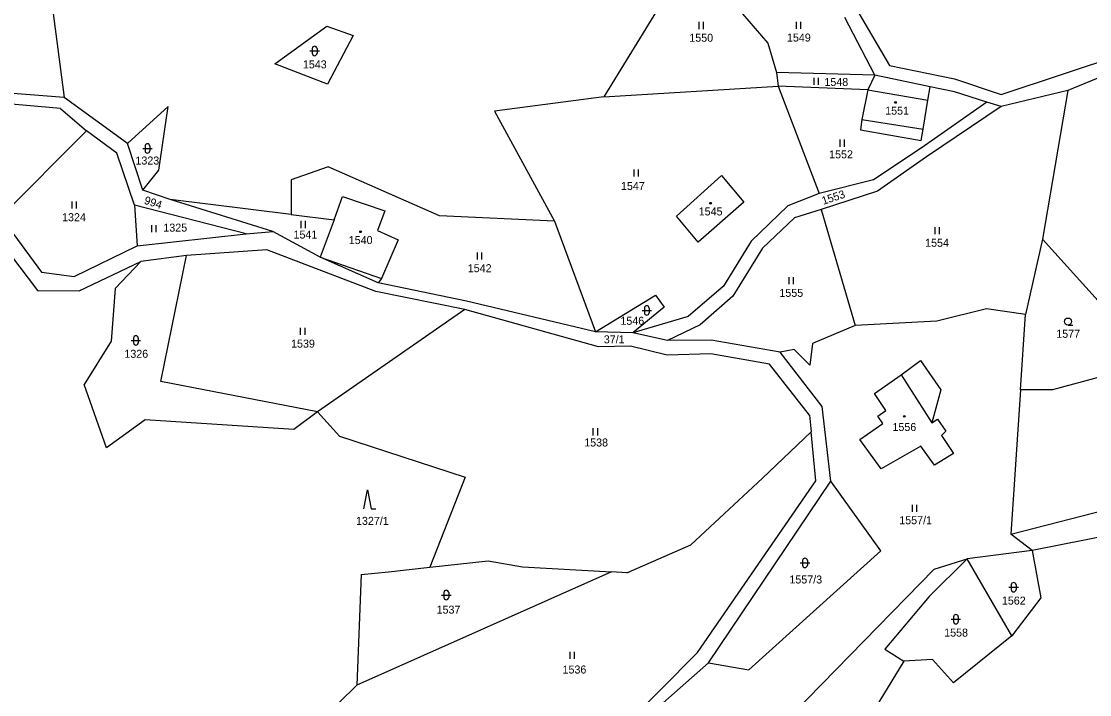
# Model space of a CAD drawing. Extents: x -670359 to -668019, y -978807 to -976674.
# Drawn here: x -669575.5 to -669348.5, y -978050.6 to -977907.6 of the extents above; entities that cross this region are included whole.
import ezdxf

# ---------------------------------------------------------------- set-up
doc = ezdxf.new("R2010")
doc.units = 0
for name, color, linetype in [('Hranice parcel', 7, 'Continuous'), ('Parcelní čísla', 7, 'Continuous'), ('Vnitřní kresba', 7, 'Continuous'), ('Značky budov', 7, 'Continuous'), ('Značky kultur', 7, 'Continuous')]:
    doc.layers.add(name, color=color, linetype=linetype)

msp = doc.modelspace()

# ---------------------------------------------------------------- linework, layer by layer
at = {"layer": 'Hranice parcel'}
for points in [[(-669572.17, -977879.31), (-669566.4, -977923.76)], [(-669430.35, -977896.52), (-669416.9, -977912.18)], [(-669435.8, -977897.58), (-669451.69, -977923.64)], [(-669394.16, -977918.98), (-669400.52, -977906.76)], [(-669397.47, -977905.99), (-669391.02, -977916.94)], [(-669521.65, -977916.57), (-669510.6, -977908.61)], [(-669510.6, -977908.61), (-669505.02, -977910.59)], [(-669505.02, -977910.59), (-669510.41, -977920.93)], [(-669416.9, -977912.18), (-669415.05, -977918.44)], [(-669367.31, -977923.11), (-669341.2, -977914.44)], [(-669510.41, -977920.93), (-669521.65, -977916.57)], [(-669391.02, -977916.94), (-669377.2, -977919.81)], [(-669339.55, -977916.69), (-669353.13, -977922.23)], [(-669415.05, -977918.44), (-669414.68, -977921.32)], [(-669394.16, -977918.98), (-669415.05, -977918.44)], [(-669394.16, -977918.98), (-669395.64, -977922.09)], [(-669382.38, -977921.45), (-669394.16, -977918.98)], [(-669451.69, -977923.64), (-669414.68, -977921.32)], [(-669414.68, -977921.32), (-669405.96, -977944.13)], [(-669395.64, -977922.09), (-669414.68, -977921.32)], [(-669382.85, -977924.3), (-669382.38, -977921.45)], [(-669377.23, -977922.53), (-669382.38, -977921.45)], [(-669377.2, -977919.81), (-669367.31, -977923.11)], [(-669566.4, -977923.76), (-669587.31, -977922.09)], [(-669552.97, -977933.51), (-669566.4, -977923.76)], [(-669451.69, -977923.64), (-669474.93, -977926.67)], [(-669395.64, -977922.09), (-669396.9, -977928.39)], [(-669370.37, -977924.76), (-669377.23, -977922.53)], [(-669353.13, -977922.23), (-669367.26, -977925.67)], [(-669353.13, -977922.23), (-669358.51, -977953.84)], [(-669567.14, -977926.07), (-669587.3, -977924.33)], [(-669567.14, -977926.07), (-669561.67, -977930.85)], [(-669544.32, -977925.68), (-669552.97, -977933.51)], [(-669546.31, -977939.18), (-669544.32, -977925.68)], [(-669370.37, -977924.76), (-669384.32, -977934.53)], [(-669383.88, -977930.45), (-669382.85, -977924.3)], [(-669367.26, -977925.67), (-669383.14, -977936.38)], [(-669367.26, -977925.67), (-669370.37, -977924.76)], [(-669474.93, -977926.67), (-669462.21, -977950)], [(-669396.9, -977928.39), (-669397.17, -977930.63)], [(-669397.17, -977930.63), (-669384.3, -977932.86)], [(-669384.3, -977932.86), (-669383.88, -977930.45)], [(-669561.67, -977930.85), (-669579.87, -977949.13)], [(-669555.23, -977935.56), (-669561.67, -977930.85)], [(-669549.71, -977943.46), (-669552.97, -977933.51)], [(-669384.32, -977934.53), (-669394.4, -977941.22)], [(-669551.43, -977946.64), (-669555.23, -977935.56)], [(-669383.14, -977936.38), (-669393.54, -977943.62)], [(-669549.71, -977943.46), (-669546.31, -977939.18)], [(-669510.28, -977938.45), (-669518.15, -977941.24)], [(-669486.61, -977948.86), (-669510.28, -977938.45)], [(-669518.15, -977941.24), (-669518.15, -977948.6)], [(-669436.26, -977949), (-669426.73, -977940.31)], [(-669426.73, -977940.31), (-669421.98, -977945.96)], [(-669394.4, -977941.22), (-669405.96, -977944.13)], [(-669543.89, -977945.44), (-669549.71, -977943.46)], [(-669405.96, -977944.13), (-669412.63, -977946.78)], [(-669393.54, -977943.62), (-669405.51, -977947.57)], [(-669527.72, -977952.73), (-669551.43, -977946.64)], [(-669551.43, -977946.64), (-669550.88, -977955.28)], [(-669518.15, -977948.6), (-669543.89, -977945.44)], [(-669522.03, -977952.24), (-669543.89, -977945.44)], [(-669509.04, -977949.72), (-669507.22, -977944.8)], [(-669507.22, -977944.8), (-669498.29, -977947.85)], [(-669421.98, -977945.96), (-669431.68, -977954.49)], [(-669518.15, -977948.6), (-669509.04, -977949.72)], [(-669498.29, -977947.85), (-669499.85, -977952)], [(-669462.21, -977950), (-669486.61, -977948.86)], [(-669412.63, -977946.78), (-669420.39, -977954.29)], [(-669405.51, -977947.57), (-669411.21, -977949.35)], [(-669405.51, -977947.57), (-669398.33, -977972.21)], [(-669579.87, -977949.13), (-669571.19, -977960.9)], [(-669509.04, -977949.72), (-669512, -977957.7)], [(-669462.21, -977950), (-669453.49, -977973.53)], [(-669431.68, -977954.49), (-669436.26, -977949)], [(-669411.21, -977949.35), (-669418.01, -977955.76)], [(-669581.59, -977952.23), (-669572.03, -977964.73)], [(-669550.88, -977955.28), (-669527.72, -977952.73)], [(-669527.72, -977952.73), (-669522.03, -977952.24)], [(-669512, -977957.7), (-669522.03, -977952.24)], [(-669499.85, -977952), (-669495.39, -977953.96)], [(-669564.24, -977961.78), (-669550.88, -977955.28)], [(-669495.39, -977953.96), (-669499, -977962.24)], [(-669420.39, -977954.29), (-669426.26, -977963.83)], [(-669358.51, -977953.84), (-669362.12, -977969.88)], [(-669334.85, -977980.09), (-669358.51, -977953.84)], [(-669540.41, -977957.32), (-669550.11, -977958.57)], [(-669545.82, -977984.13), (-669540.41, -977957.32)], [(-669523.35, -977956.14), (-669540.41, -977957.32)], [(-669500.15, -977964.95), (-669523.35, -977956.14)], [(-669499.65, -977963.12), (-669512, -977957.7)], [(-669418.01, -977955.76), (-669424.28, -977965.93)], [(-669563.23, -977964.83), (-669550.11, -977958.57)], [(-669550.11, -977958.57), (-669555.54, -977964.35)], [(-669571.19, -977960.9), (-669564.24, -977961.78)], [(-669499, -977962.24), (-669499.65, -977963.12)], [(-669572.03, -977964.73), (-669563.23, -977964.83)], [(-669555.54, -977964.35), (-669556.38, -977975.54)], [(-669480.89, -977967.05), (-669499.65, -977963.12)], [(-669426.26, -977963.83), (-669433.77, -977970.31)], [(-669481.25, -977968.81), (-669500.15, -977964.95)], [(-669453.49, -977973.53), (-669480.89, -977967.05)], [(-669453.49, -977973.53), (-669440.76, -977965.75)], [(-669440.76, -977965.75), (-669438.87, -977968.33)], [(-669424.28, -977965.93), (-669431.23, -977972.09)], [(-669481.25, -977968.81), (-669512.59, -977990.57)], [(-669452.89, -977976.74), (-669481.25, -977968.81)], [(-669438.87, -977968.33), (-669445.57, -977973.78)], [(-669370.43, -977968.67), (-669380.95, -977971.28)], [(-669362.12, -977969.88), (-669370.43, -977968.67)], [(-669433.77, -977970.31), (-669445.57, -977973.78)], [(-669380.95, -977971.28), (-669398.33, -977972.21)], [(-669363.17, -977985.86), (-669362.12, -977969.88)], [(-669445.57, -977973.78), (-669453.49, -977973.53)], [(-669438.22, -977975.38), (-669445.57, -977973.78)], [(-669431.23, -977972.09), (-669438.22, -977975.38)], [(-669398.33, -977972.21), (-669407.41, -977976.03)], [(-669556.38, -977975.54), (-669562.16, -977984.76)], [(-669428.94, -977975.32), (-669438.22, -977975.38)], [(-669414.24, -977977.87), (-669428.94, -977975.32)], [(-669407.41, -977976.03), (-669407.94, -977980.66)], [(-669446.08, -977976.57), (-669452.89, -977976.74)], [(-669438.26, -977978.5), (-669446.08, -977976.57)], [(-669428.97, -977978.2), (-669438.26, -977978.5)], [(-669416.5, -977980.41), (-669428.97, -977978.2)], [(-669411.27, -977977.27), (-669414.24, -977977.87)], [(-669405.31, -977989.41), (-669414.24, -977977.87)], [(-669407.94, -977980.66), (-669411.27, -977977.27)], [(-669408.05, -977991.22), (-669416.5, -977980.41)], [(-669388.51, -977982.71), (-669384.4, -977979.64)], [(-669384.4, -977979.64), (-669380.14, -977985.84)], [(-669334.85, -977980.09), (-669356.37, -977985.86)], [(-669394.24, -977986.65), (-669388.51, -977982.71)], [(-669557.42, -977998.16), (-669562.16, -977984.76)], [(-669512.59, -977990.57), (-669545.82, -977984.13)], [(-669391.79, -977990.27), (-669394.24, -977986.65)], [(-669380.14, -977985.84), (-669382.06, -977992.86)], [(-669363.17, -977985.86), (-669365.21, -978016.55)], [(-669356.37, -977985.86), (-669363.17, -977985.86)], [(-669403.48, -978005.27), (-669405.31, -977989.41)], [(-669512.59, -977990.57), (-669517.59, -977994.28)], [(-669512.59, -977990.57), (-669507.92, -977995.74)], [(-669408.05, -977991.22), (-669407.7, -977994.81)], [(-669393.5, -977991.5), (-669391.79, -977990.27)], [(-669392.46, -977992.99), (-669393.5, -977991.5)], [(-669549.19, -977992.25), (-669557.42, -977998.16)], [(-669517.59, -977994.28), (-669549.19, -977992.25)], [(-669397.36, -977996.4), (-669392.46, -977992.99)], [(-669382.06, -977992.86), (-669380.85, -977992.07)], [(-669380.85, -977992.07), (-669379.03, -977994.65)], [(-669507.92, -977995.74), (-669481.2, -978004.43)], [(-669418.03, -978004.65), (-669407.7, -977994.81)], [(-669406.68, -978005.23), (-669407.7, -977994.81)], [(-669392.81, -978002.66), (-669397.36, -977996.4)], [(-669379.03, -977994.65), (-669380, -977995.6)], [(-669380, -977995.6), (-669377.4, -977999.39)], [(-669384.35, -977997.87), (-669392.81, -978002.66)], [(-669381.43, -978001.9), (-669384.35, -977997.87)], [(-669377.4, -977999.39), (-669381.43, -978001.9)], [(-669365.21, -978016.55), (-669297.15, -977999.02)], [(-669481.2, -978004.43), (-669488.69, -978023.58)], [(-669433.25, -978018.84), (-669418.03, -978004.65)], [(-669431.8, -978041.67), (-669406.68, -978005.23)], [(-669429.5, -978043.86), (-669403.48, -978005.27)], [(-669392.85, -978020.07), (-669403.48, -978005.27)], [(-669330.97, -978014.13), (-669360.73, -978020.04)], [(-669360.73, -978020.04), (-669365.21, -978016.55)], [(-669446.84, -978024.76), (-669433.25, -978018.84)], [(-669420.9, -978045.39), (-669392.85, -978020.07)], [(-669360.73, -978020.04), (-669374.52, -978021.81)], [(-669360.73, -978020.04), (-669358.83, -978030.06)], [(-669497.51, -978024.54), (-669488.69, -978023.58)], [(-669488.69, -978023.58), (-669476.29, -978022.24)], [(-669476.29, -978022.24), (-669469.02, -978023.48)], [(-669469.02, -978023.48), (-669450.07, -978024.57)], [(-669374.52, -978021.81), (-669382.61, -978029.81)], [(-669381.54, -978024), (-669374.52, -978021.81)], [(-669365, -978038.15), (-669374.52, -978021.81)], [(-669450.07, -978024.57), (-669504.24, -978048.65)], [(-669503.27, -978025.14), (-669504.24, -978048.65)], [(-669503.27, -978025.14), (-669497.51, -978024.54)], [(-669446.84, -978024.76), (-669450.07, -978024.57)], [(-669414.36, -978057.64), (-669381.54, -978024)], [(-669382.61, -978029.81), (-669392.01, -978040.98)], [(-669358.83, -978030.06), (-669365, -978038.15)], [(-669365, -978038.15), (-669377.44, -978048.1)], [(-669447.74, -978057.74), (-669431.8, -978041.67)], [(-669392.01, -978040.98), (-669387.95, -978043.51)], [(-669446.99, -978059.3), (-669429.5, -978043.86)], [(-669429.5, -978043.86), (-669420.9, -978045.39)], [(-669387.95, -978043.51), (-669416.42, -978090.19)], [(-669381.87, -978043.17), (-669387.95, -978043.51)], [(-669377.44, -978048.1), (-669381.87, -978043.17)], [(-669504.24, -978048.65), (-669511.76, -978056.09)]]:
    msp.add_lwpolyline(points, dxfattribs=at)
at = {"layer": 'Vnitřní kresba'}
for points in [[(-669395.64, -977922.09), (-669382.85, -977924.3)], [(-669396.9, -977928.39), (-669383.88, -977930.45)], [(-669512, -977957.7), (-669499, -977962.24)], [(-669388.51, -977982.71), (-669382.06, -977992.86)]]:
    msp.add_lwpolyline(points, dxfattribs=at)
at = {"layer": 'Značky budov'}
for centre in [(-669389.76, -977924.8), (-669429.06, -977946.21), (-669503.42, -977952.29), (-669387.87, -977991.51)]:
    msp.add_circle(centre, 0.175, dxfattribs=at)
at = {"layer": 'Značky kultur'}
for p, q in [((-669431.56, -977907.7), (-669431.56, -977909.2)), ((-669430.56, -977909.2), (-669430.56, -977907.7)), ((-669410.85, -977907.66), (-669410.85, -977909.16)), ((-669409.85, -977909.16), (-669409.85, -977907.66)), ((-669514.17, -977913.86), (-669512.17, -977913.86)), ((-669513.67, -977913.36), (-669513.67, -977914.36)), ((-669512.67, -977913.36), (-669512.67, -977914.36)), ((-669407.12, -977919.54), (-669407.12, -977921.04)), ((-669406.12, -977921.04), (-669406.12, -977919.54)), ((-669401.59, -977932.7), (-669401.59, -977934.2)), ((-669400.59, -977934.2), (-669400.59, -977932.7)), ((-669549.71, -977934.58), (-669547.71, -977934.58)), ((-669549.21, -977934.08), (-669549.21, -977935.08)), ((-669548.21, -977934.08), (-669548.21, -977935.08)), ((-669445.34, -977939.05), (-669445.34, -977940.55)), ((-669444.34, -977940.55), (-669444.34, -977939.05)), ((-669564.8, -977945.83), (-669564.8, -977947.33)), ((-669563.8, -977947.33), (-669563.8, -977945.83)), ((-669547.87, -977950.85), (-669547.87, -977952.35)), ((-669546.87, -977952.35), (-669546.87, -977950.85)), ((-669516.1, -977949.99), (-669516.1, -977951.49)), ((-669515.1, -977951.49), (-669515.1, -977949.99)), ((-669381.41, -977951.27), (-669381.41, -977952.77)), ((-669380.41, -977952.77), (-669380.41, -977951.27)), ((-669478.63, -977956.67), (-669478.63, -977958.17)), ((-669477.63, -977958.17), (-669477.63, -977956.67)), ((-669412.42, -977961.91), (-669412.42, -977963.41)), ((-669411.42, -977963.41), (-669411.42, -977961.91)), ((-669443.61, -977968.99), (-669441.61, -977968.99)), ((-669443.11, -977968.49), (-669443.11, -977969.49)), ((-669442.11, -977968.49), (-669442.11, -977969.49)), ((-669516.22, -977972.7), (-669516.22, -977974.2)), ((-669515.22, -977974.2), (-669515.22, -977972.7)), ((-669353.09, -977972.11), (-669352.09, -977972.11)), ((-669552.14, -977975.36), (-669550.14, -977975.36)), ((-669551.64, -977974.86), (-669551.64, -977975.86)), ((-669550.64, -977974.86), (-669550.64, -977975.86)), ((-669454.03, -977994.04), (-669454.03, -977995.54)), ((-669453.03, -977995.54), (-669453.03, -977994.04)), ((-669386.21, -978010.29), (-669386.21, -978011.79)), ((-669385.21, -978011.79), (-669385.21, -978010.29)), ((-669409.98, -978022.65), (-669407.98, -978022.65)), ((-669409.48, -978022.15), (-669409.48, -978023.15)), ((-669408.48, -978022.15), (-669408.48, -978023.15)), ((-669365.64, -978027.81), (-669363.64, -978027.81)), ((-669365.14, -978027.31), (-669365.14, -978028.31)), ((-669364.14, -978027.31), (-669364.14, -978028.31)), ((-669486.19, -978029.47), (-669484.19, -978029.47)), ((-669485.69, -978028.97), (-669485.69, -978029.97)), ((-669484.69, -978028.97), (-669484.69, -978029.97)), ((-669377.9, -978034.61), (-669375.9, -978034.61)), ((-669377.4, -978034.11), (-669377.4, -978035.11)), ((-669376.4, -978034.11), (-669376.4, -978035.11)), ((-669458.93, -978041.54), (-669458.93, -978043.04)), ((-669457.93, -978043.04), (-669457.93, -978041.54))]:
    msp.add_line(p, q, dxfattribs=at)
msp.add_lwpolyline([(-669502.69, -978011.13), (-669501.94, -978007.13), (-669501.19, -978011.13), (-669500.19, -978011.13)], dxfattribs=at)
for centre, radius in [((-669389.76, -977924.8), 0.175), ((-669429.06, -977946.21), 0.175), ((-669503.42, -977952.29), 0.175), ((-669353.09, -977971.36), 0.75), ((-669387.87, -977991.51), 0.175)]:
    msp.add_circle(centre, radius, dxfattribs=at)
for centre, start, end in [((-669513.17, -977913.36), 0, 180), ((-669513.17, -977914.36), 180, 0), ((-669548.71, -977934.08), 0, 180), ((-669548.71, -977935.08), 180, 0), ((-669442.61, -977968.49), 0, 180), ((-669442.61, -977969.49), 180, 0), ((-669551.14, -977974.86), 0, 180), ((-669551.14, -977975.86), 180, 0), ((-669408.98, -978022.15), 0, 180), ((-669408.98, -978023.15), 180, 0), ((-669364.64, -978027.31), 0, 180), ((-669364.64, -978028.31), 180, 0), ((-669485.19, -978028.97), 0, 180), ((-669485.19, -978029.97), 180, 0), ((-669376.9, -978034.11), 0, 180), ((-669376.9, -978035.11), 180, 0)]:
    msp.add_arc(centre, 0.5, start, end, dxfattribs=at)

# ---------------------------------------------------------------- texts
at = {"layer": 'Parcelní čísla'}
for s, p in [('1550', (-669433.56, -977911.9)), ('1549', (-669412.81, -977911.86)), ('1543', (-669515.67, -977917.56)), ('1548', (-669404.85, -977921.3)), ('1551', (-669391.94, -977927.4)), ('1552', (-669403.85, -977936.68)), ('1323', (-669551.25, -977937.99)), ('1547', (-669448.08, -977943.4)), ('1324', (-669566.84, -977950.03)), ('1545', (-669431.56, -977948.81)), ('1325', (-669545.32, -977952.25)), ('1541', (-669517.66, -977953.72)), ('1540', (-669505.92, -977954.89)), ('1554', (-669383.45, -977955.47)), ('1542', (-669480.63, -977960.87)), ('1555', (-669414.42, -977966.11)), ('1546', (-669448.2, -977972.05)), ('1577', (-669355.59, -977974.81)), ('1539', (-669518.18, -977976.9)), ('37/1', (-669451.73, -977975.99)), ('1326', (-669553.6, -977979.06)), ('1556', (-669390.39, -977994.62)), ('1538', (-669455.89, -977997.91)), ('1327/1', (-669504.38, -978014.56)), ('1557/1', (-669388.95, -978014.43)), ('1557/3', (-669412.29, -978027.02)), ('1562', (-669367.14, -978031.51)), ('1537', (-669487.26, -978033.43)), ('1558', (-669379.4, -978038.31)), ('1536', (-669460.5, -978046.15))]:
    msp.add_text(s, height=1.7, dxfattribs=at).set_placement(p)
for s, rotation, p in [('1553', 18.317, (-669405.09, -977946.57)), ('994', 342.1598, (-669549.54, -977946.29))]:
    msp.add_text(s, height=1.7, rotation=rotation, dxfattribs=at).set_placement(p)

doc.saveas('drawing.dxf')
